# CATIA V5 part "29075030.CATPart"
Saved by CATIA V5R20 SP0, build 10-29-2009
Part number: 29075030
Definition: NONE
Nomenclature: 29075030
Source: Unknown
Description: 29075030
Bounding box of the stored display mesh (mm): x -15 to 44.548, y -51.5 to 86.048, z -41.5 to 41.5
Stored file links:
  C:\Users\Utente\Desktop\IO LAVORO\3D X SITO CF\X SITO\PLASTICA\RF1\29075030.CATPart
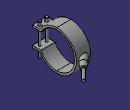
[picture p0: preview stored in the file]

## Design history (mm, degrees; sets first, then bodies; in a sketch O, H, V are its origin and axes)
Body1 "29075030" (main body)
  Solid1: solid without history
